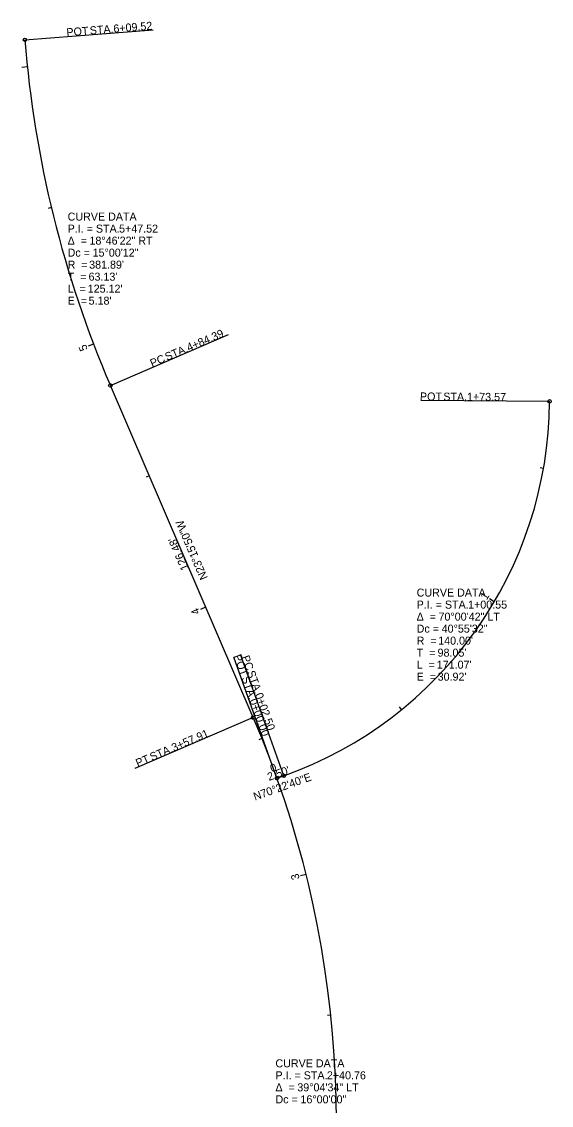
# Model space of a CAD drawing. Extents: x 1821160 to 1822741, y 497996 to 498758.
# Drawn here: x 1821927.1 to 1822112.3, y 498378.6 to 498757.7 of the extents above; entities that cross this region are included whole.
import ezdxf

# ---------------------------------------------------------------- set-up
doc = ezdxf.new("R2010")
doc.units = 0
for name, color, linetype in [('LT_X_Luminaires', 7, 'Continuous'), ('SC_Scratch1', 7, 'Continuous'), ('SC_Scratch20', 7, 'Continuous'), ('SV_P_Mon_Cells_Set', 7, 'Continuous'), ('SV_X_Control_Cells_Found', 7, 'Continuous'), ('SV_X_Mon_Cells_Found', 7, 'Continuous')]:
    doc.layers.add(name, color=color, linetype=linetype)

msp = doc.modelspace()

# ---------------------------------------------------------------- linework, layer by layer
at = {"layer": 'SC_Scratch1'}
for p, q in [((1821929.05, 498741.85), (1821927.06, 498741.65)), ((1821937.44, 498692.6), (1821936.28, 498692.32)), ((1821952.2, 498644.86), (1821950.33, 498644.15)), ((1822109.55, 498601.4), (1822108.36, 498601.61)), ((1821971.65, 498598.81), (1821970.55, 498598.33)), ((1822092.34, 498554.73), (1822090.61, 498555.75)), ((1821991.4, 498552.87), (1821989.56, 498552.08)), ((1822059.9, 498517.03), (1822059.15, 498517.96)), ((1822011.07, 498506.9), (1822009.95, 498506.45)), ((1822016.34, 498493.03), (1822015.67, 498494.91)), ((1822026.5, 498459.39), (1822024.56, 498458.91)), ((1822035.18, 498410.19), (1822033.98, 498410.06))]:
    msp.add_line(p, q, dxfattribs=at)
at = {"layer": 'SV_P_Mon_Cells_Set'}
for p, q in [((1822008.02, 498514.21), (1821958.07, 498630.4)), ((1822016.34, 498493.03), (1822018.69, 498493.86))]:
    msp.add_line(p, q, dxfattribs=at)
for centre, radius, start, end in [((1822308.91, 498781.24), 381.89, 184.4912, 203.264), ((1821971.68, 498625.73), 140, 289.6224, 359.6341), ((1821679.04, 498372.77), 358.1, 344.1879, 23.264)]:
    msp.add_arc(centre, radius, start, end, dxfattribs=at)
at = {"layer": 'SV_X_Control_Cells_Found'}
for p, q in [((1821928.19, 498751.33), (1821973.05, 498754.86)), ((1821958.07, 498630.4), (1821999.41, 498648.18)), ((1822111.67, 498624.84), (1822066.68, 498625.13)), ((1822016.34, 498493.03), (1822001.23, 498535.41)), ((1822018.69, 498493.86), (1822003.58, 498536.25)), ((1822008.02, 498514.21), (1821966.68, 498496.43))]:
    msp.add_line(p, q, dxfattribs=at)
for centre in [(1821928.19, 498751.33), (1821958.07, 498630.4), (1822111.67, 498624.84), (1822008.02, 498514.21), (1822016.34, 498493.03), (1822018.69, 498493.86)]:
    msp.add_circle(centre, 0.6, dxfattribs=at)

# ---------------------------------------------------------------- texts
at = {"layer": 'LT_X_Luminaires'}
for s, p in [('CURVE DATA', (1821943.13, 498688.07)), ('P.I. = STA. ', (1821943.13, 498683.87)), ('5+47.52', (1821961.12, 498683.87)), ('Δ  = ', (1821943.13, 498679.67)), ('18°46\'22" RT', (1821950.77, 498679.67)), ('Dc = ', (1821943.13, 498675.47)), ('15°00\'12"', (1821951.87, 498675.47)), ('R  = ', (1821943.13, 498671.27)), ("381.89'", (1821950.66, 498671.27)), ('T  = ', (1821943.13, 498667.07)), ("63.13'", (1821950.45, 498667.07)), ('L  = ', (1821943.13, 498662.87)), ("125.12'", (1821950.16, 498662.87)), ('E  = ', (1821943.13, 498658.67)), ("5.18'", (1821950.47, 498658.67)), ('CURVE DATA', (1822065.18, 498556.55)), ('P.I. = STA. ', (1822065.18, 498552.35)), ('1+00.55', (1822083.17, 498552.35)), ('Δ  = ', (1822065.18, 498548.15)), ('70°00\'42" LT', (1822072.83, 498548.15)), ('Dc = ', (1822065.18, 498543.95)), ('40°55\'32"', (1822073.93, 498543.95)), ('R  = ', (1822065.18, 498539.75)), ("140.00'", (1822072.72, 498539.75)), ('T  = ', (1822065.18, 498535.55)), ("98.05'", (1822072.5, 498535.55)), ('L  = ', (1822065.18, 498531.35)), ("171.07'", (1822072.22, 498531.35)), ('E  = ', (1822065.18, 498527.15)), ("30.92'", (1822072.53, 498527.15)), ('CURVE DATA', (1822015.8, 498391.9)), ('P.I. = STA. ', (1822015.8, 498387.7)), ('2+40.76', (1822033.79, 498387.7)), ('Δ  = ', (1822015.8, 498383.5)), ('39°04\'34" LT', (1822023.45, 498383.5)), ('Dc = ', (1822015.8, 498379.3)), ('16°00\'00"', (1822024.55, 498379.3))]:
    msp.add_text(s, height=2.8, dxfattribs=at).set_placement(p)
at = {"layer": 'SC_Scratch1'}
for s, rotation, p in [('5', 110.9223, (1821950.21, 498643.06)), ('1', 59.5261, (1822089.68, 498555.15)), ('4', 113.264, (1821989.51, 498550.92)), ('0', 19.6224, (1822014.53, 498495.03)), ('3', 103.9979, (1822024.31, 498457.85))]:
    msp.add_text(s, height=2.8, rotation=rotation, dxfattribs=at).set_placement(p)
at = {"layer": 'SC_Scratch20'}
for s, rotation, p in [("126.48'", 113.264, (1821985.55, 498566.38)), ("2.50'", 19.6224, (1822013.55, 498492.07))]:
    msp.add_text(s, height=2.8, rotation=rotation, dxfattribs=at).set_placement(p)
at = {"layer": 'SV_X_Control_Cells_Found'}
for s, rotation, p in [('POT', 4.4912, (1821942.83, 498752.52)), (' STA. ', 4.4912, (1821949.94, 498753.08)), ('6+09.52', 4.4912, (1821959.23, 498753.81)), ('4+84.39', 23.264, (1821985.49, 498642.23)), ('PC', 23.264, (1821972.69, 498636.73)), (' STA. ', 23.264, (1821976.92, 498638.55)), ('POT', 359.6341, (1822066.33, 498625.17)), (' STA. ', 359.6341, (1822073.46, 498625.12)), ('1+73.57', 359.6341, (1822082.79, 498625.06)), ('POT', 289.6224, (1822001.14, 498535.77)), ('PC', 289.6224, (1822003.92, 498535.42)), (' STA. ', 289.6224, (1822003.53, 498529.06)), (' STA. ', 289.6224, (1822005.46, 498531.08)), ('0+00.00', 289.6224, (1822006.66, 498520.27)), ('0+02.50', 289.6224, (1822008.59, 498522.3)), ('3+57.91', 23.264, (1821980.21, 498502.29)), ('PT', 23.264, (1821967.65, 498496.89)), (' STA. ', 23.264, (1821971.64, 498498.61))]:
    msp.add_text(s, height=2.8, rotation=rotation, dxfattribs=at).set_placement(p)
at = {"layer": 'SV_X_Mon_Cells_Found'}
for s, rotation, p in [('N23°15\'50"W', 113.264, (1821992.2, 498563.15)), ('N70°22\'40"E', 19.6224, (1822008.66, 498485.19))]:
    msp.add_text(s, height=2.8, rotation=rotation, dxfattribs=at).set_placement(p)

doc.saveas('drawing.dxf')
